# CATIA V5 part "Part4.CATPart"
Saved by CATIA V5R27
Part number: Part4
Bounding box of the stored display mesh (mm): x -5.498 to 5.498, y -40 to 13, z 113.002 to 123.998
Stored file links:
  E:\university\my-thesis\My Thesis Publication\Final-Updata\CAD\Part4.CATPart
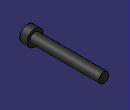
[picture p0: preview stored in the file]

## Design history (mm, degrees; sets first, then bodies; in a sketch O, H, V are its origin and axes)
Set1
  Sketch1 on yz-plane, origin (0, 0, 0), H (0, 1, 0), V (0, 0, 1)
    line L1 (13, 118.5) -> (-40, 118.5)
    point P2 (-40, 118.5)
    line L2 (-40, 118.5) -> (-40, 114)
    point P3 (-40, 113)
    line L3 (-39, 113) -> (-34, 113)
    point P4 (-34, 113)
    line L4 (-34, 113) -> (-34, 115)
    line L5 (-34, 115) -> (13, 115)
    line L6 (13, 115) -> (13, 118.5)
    reference intersected line E1 through (0, 0) direction (0, 1) from zx-plane
    point P7 (3, 128)
    arc A1 centre (-39, 114) radius 1 from (-39, 113) to (-40, 114) cw
    length L1 = 53
    length L6 = 3.5
    distance L2 E1 = 40
    distance L1 P7 = 9.5
    distance P3 P4 = 6
    distance P2 P3 = 5.5
    radius A1 = 1
    horizontal: L1 H, L3 H, L5 H
    vertical: L2 V, L4 V, L6 V
    coincidence: L3 P3, L2 P3
    tangency: A1 L3, A1 L2
  DatumCurve1
  Sketch2 on face of Shaft1 from Sketch1.L2, origin (0, -40, 0), H (1, 0, 0), V (0, 0, 1)
    point P1 (0, 118.5)
    point P2 (0.8037, 121.4226)
    construction circle A1 centre (0, 118.5) radius 3.5
    construction circle A2 centre (0, 118.5) radius 3.0311
    point P3 (2.491, 120.9586)
    point P4 (-0.8837, 121.8866)
    point P5 (-3.3747, 119.428)
    point P6 (-2.491, 116.0414)
    point P7 (0.8837, 115.1134)
    point P8 (3.3747, 117.572)
    line L1 (2.491, 120.9586) -> (-0.8837, 121.8866)
    line L2 (-0.8837, 121.8866) -> (-3.3747, 119.428)
    line L3 (-3.3747, 119.428) -> (-2.491, 116.0414)
    line L4 (-2.491, 116.0414) -> (0.8837, 115.1134)
    line L5 (0.8837, 115.1134) -> (3.3747, 117.572)
    line L6 (3.3747, 117.572) -> (2.491, 120.9586)
    construction line L7 (0, 118.5) -> (0.8037, 121.4226)
    reference projected circle E1 centre (0, 118.5) radius 4.5 from edge [face of Shaft1 from Sketch1.A1 | face of Shaft1 from Sketch1.L2]
    length L6 = 3.5
    coincidence: A1 P3, A1 P4, A1 P5, A1 P6, A1 P7, A1 P8, P1 V
    tangency: A2 L1, A2 L2, A2 L3, A2 L4, A2 L5, A2 L6
    midpoint: P2 L1
    concentricity: P1 E1
Body1 (main body)
  Shaft1: profile Sketch1, axis Sketch1.L1, angle 360
  Pocket1: profile Sketch2, direction (0, 1, 0), length 3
